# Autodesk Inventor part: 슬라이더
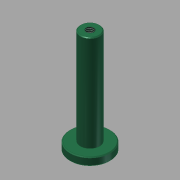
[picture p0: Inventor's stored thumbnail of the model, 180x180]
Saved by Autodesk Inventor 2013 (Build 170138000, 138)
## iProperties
Created: 2016-02
Part Number: 슬라이더
Material: 스테인리스강
Document SubType Name: Modeling
Designer: mduedu
Density: 8.08 g/cm^3
Author: mduedu
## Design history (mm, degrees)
sketch "스케치1"
  geometry: C1 r 12.5 at (0, 0); 1 further point
  constraints: 1 centre point, 1 coincident
  dimensions: "d0" = 25 diameter of C1
extrude "돌출1" new body sketch "스케치1" distance "d1" = 5; taper "d2" = 0 deg
sketch "스케치2"
  geometry: C1 r 6 at (0, 0); 1 further point
  constraints: 1 centre point, 1 coincident
  dimensions: "d3" = 12 diameter of C1
extrude "돌출2" join sketch "스케치2" distance "d4" = 60; taper "d5" = 0 deg
chamfer "모따기1" distance "d6" = 0.5; stored, may be unused: second distance "d7" = 2, angle "d8" = 45 deg
hole "구멍1" diameter "d11" = 4.917; stored, may be unused: countersink angle "d15" = 90 deg, drill point angle "d17" = 118 deg; dims "d9" = 10, "d10" = 10, "d12" = 10, "d13" = 4, "d14" = 2, "d16" = 12
chamfer "모따기2" distance "d18" = 0.5; stored, may be unused: second distance "d19" = 2, angle "d20" = 45 deg
node "솔리드1"
